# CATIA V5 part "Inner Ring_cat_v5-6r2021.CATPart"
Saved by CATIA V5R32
Part number: Inner Ring
Bounding box of the stored display mesh (mm): x -69.981 to 69.981, y 0 to 50, z -69.908 to 69.908
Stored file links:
  D:\PROJECTS\Project 2022\CATIA V5 6R 2022\Resources\Tutorial Files\c16_catia_v5_6r2022_tut\Bearing\Inner Ring_cat_v5-6r2021.CATPart
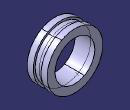
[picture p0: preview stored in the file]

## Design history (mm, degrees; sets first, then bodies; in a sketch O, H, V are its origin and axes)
Body1 (main body)
  Sketch1 on yz-plane, origin (0, 0, 0), H (0, 1, 0), V (0, 0, 1)
    point P1 (0, 50)
    line L1 (0, 50) -> (0, 70)
    line L2 (0, 70) -> (15, 70)
    line L3 (15, 70) -> (15, 65)
    line L4 (15, 65) -> (35, 65)
    line L5 (35, 65) -> (35, 70)
    point P6 (35, 70)
    line L6 (35, 70) -> (50, 70)
    line L7 (50, 70) -> (50, 50)
    line L8 (50, 50) -> (0, 50)
    distance L8 H = 50
    length L8 = 50
    length L6 = 15
    length L2 = 15
    length L7 = 20
    distance L8 L4 = 15
    coincidence: P1 V, P6 L2
    vertical: L1 V, L3 V, L5 V, L7 V
    horizontal: L2 H, L4 H, L6 H, L8 H
  Shaft1: profile Sketch1, axis Sketch1.H, angle 360
  Plane1: type Offset, RefPlane face of Shaft1 from Sketch1.L3, Offset 10, reversed
  Sketch2 on Plane1, origin (0, 25, 0), H (1, 0, 0), V (0, 0, 1)
    projected circle E1 centre (0, 0) radius 65 from edge [face of Shaft1 from Sketch1.L4 | face of Shaft1 from Sketch1.L5]
  Point1: type OnCurve, Support Sketch2, RefPoint {extremum Reference Sketch2, Direction (1, 2, 3)}, Length 192.617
